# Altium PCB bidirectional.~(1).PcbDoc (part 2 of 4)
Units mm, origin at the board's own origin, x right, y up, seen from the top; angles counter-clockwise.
Board outline 190.5 x 127 mm, 6 copper layers (Top Layer, MidLayer1, MidLayer2, Mid-Layer 3, Mid-Layer 4, Bottom Layer), stack 2.997 mm thick; 416 components, 178 nets, 1084 pads, 2010 vias.
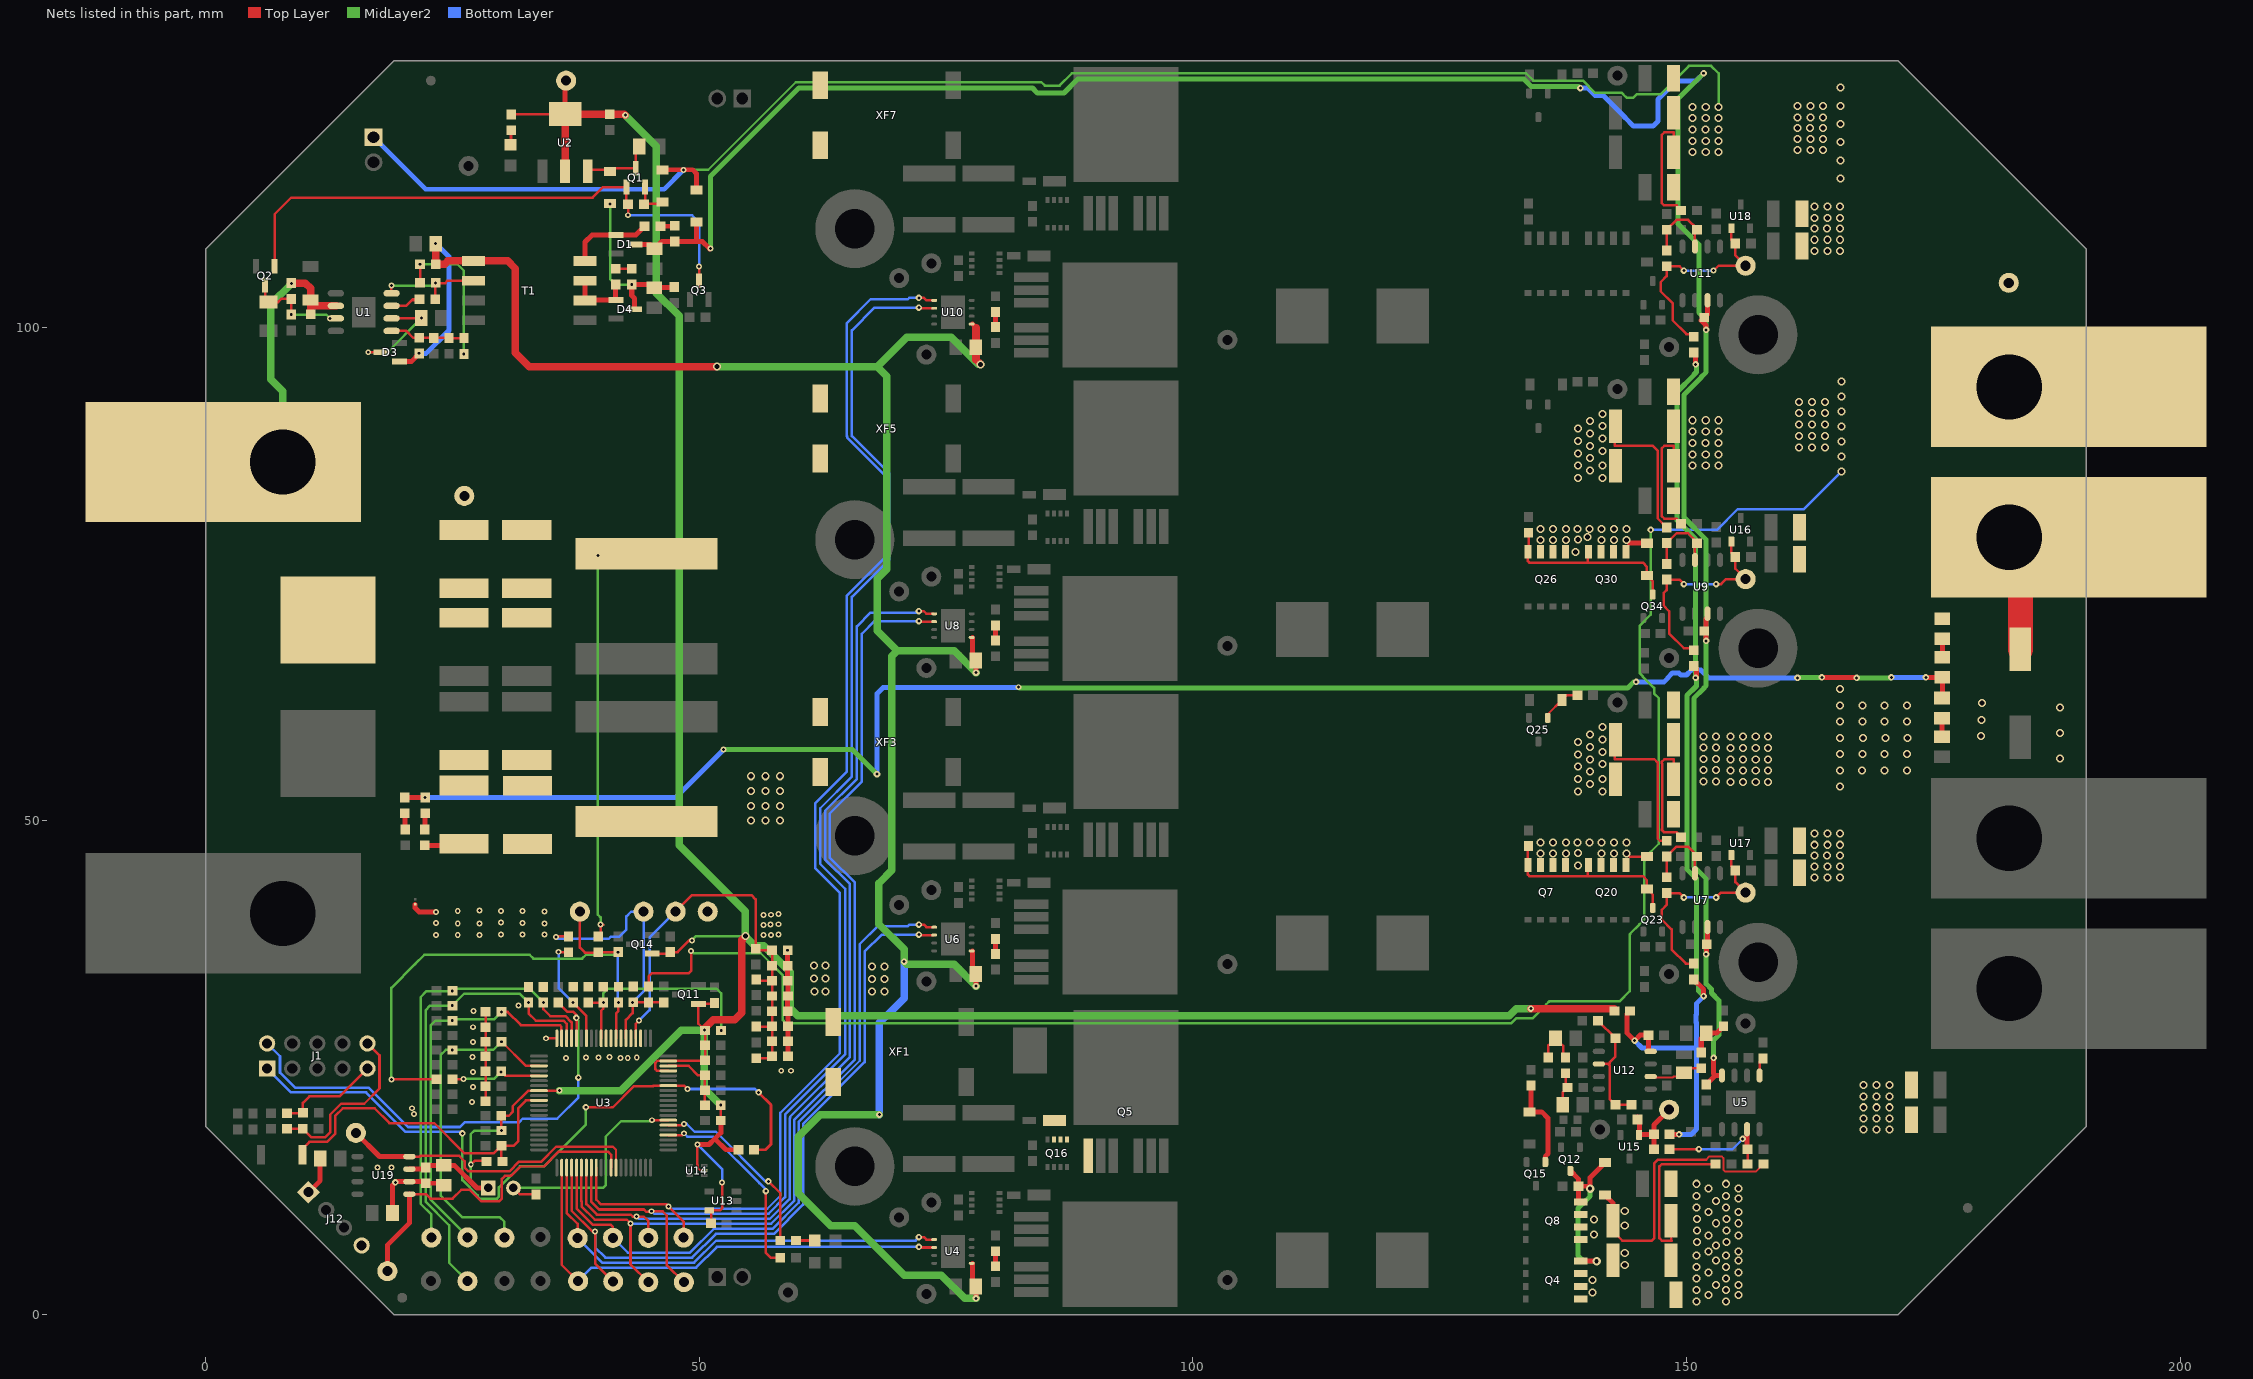
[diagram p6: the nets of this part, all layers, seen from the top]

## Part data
C1: "CAP, CERM, 3300pF, 100V, +/-5%, X7R, 0603"
C2 C8 C11: "CAP, CERM, 10uF, 16V, +/-20%, X5R, 0805"
C3: "CAP, CERM, 0.1uF, 50V, +/-10%, X7R, 0603"
C4 C28 C91 C93 C95 C97: "CAP, CERM, 0.1uF, 25V, +/-5%, X7R, 0603"
C5 C10 C114: "CAP, CERM, 100pF, 50V, +/-5%, C0G/NP0, 0603"
C6: "CAP, CERM, 2.2uF, 100V, +/-10%, X7R, 1206_190"
C7: "CAP, CERM, 0.47uF, 100V, +/-10%, X7R, 1206"
C9 C61 C70 C79 C88 C99 C100 C101 C102: "CAP, CERM, 2.2uF, 16V, +/-10%, X5R, 0805"
C12: "CAP, CERM, 10uF, 25V, +/-10%, X5R, 0805"
C13: "CAP, CERM, 10uF, 6.3V, +/-20%, X5R, 0603"
C14 C15: "CAP, CERM, 33pF, 100V, +/-5%, C0G/NP0, 0603"
C16 C25 C27 C63 C72 C81 C115: "CAP, CERM, 0.01uF, 100V, +/-5%, X7R, 0603"
C17 C20 C23: "CAP, CERM, 1uF, 16V, +/-10%, X5R, 0603"
C18 C19 C21 C24 C90: "CAP, CERM, 0.1uF, 16V, +/-5%, X7R, 0603"
C22 C71 C80 C89 C94: "CAP, CERM, 2.2uF, 10V, +/-10%, X5R, 0603"
C26 C103: "CAP, CERM, 0.022uF, 25V, +/-10%, X7R, 0603"
C29 C30 C31: "CAP, CERM, 2.2uF, 6.3V, +/-10%, X5R, 0603"
C32 C34 C35 C36 C104: "CAP, CERM, 22pF, 50V, +/-5%, C0G/NP0, 0603"
C33: "CAP, CERM, 100pF, 25V, +/-10%, X7R, 0603"
C37 C38 C40 C41 C49 C50 C52 C53: "CAP, CERM, 22uF, 50V, +/-20%, X5R, 6x5x5mm"
C39 C60 C69 C78 C87: "CAP, CERM, 0.1uF, 25V, +/-10%, X7R, 0603"
C39 C45 C51 C57: "CAP, CERM, 1000pF, 100V, +/-5%, X7R, 0603"
C42 C54 C64 C66 C73 C75 C82 C84: "CAP, CERM, 10uF, 100V, +/-20%, X7S, 2220"
C43 C46 C55 C58: "CAP, CERM, 1uF, 16V, +/-10%, X7R, 0805"
C44 C56 C65 C67 C74 C76 C83 C85 C116 C117 C118 C119 C120 C121 C122 C123: "CAP, CERM, 47uF, 16V, +/-20%, X5R, 1210"
C47: "CAP, AL, 330uF, 100V, +/-20%,  ohm, SMD"
C48: "CAP, AL, 470uF, 25V, +/-20%,  ohm, SMD"
C59 C68 C77 C86: "CAP, CERM, 330pF, 50V, +/-5%, C0G/NP0, 0603"
C62: "CAP, CERM, 4.7uF, 25V, +/-10%, X5R, 0805"
C105: "CAP, CERM, 330pF, 100V, +/-5%, X7R, 0603"
C106 C108 C109 C112: "CAP, CERM, 1 µF, 25 V, +/- 10%, X7R, 0603_095"
C107 C110 C111 C113: "CAP, CERM, 1000 pF, 50 V, +/- 10%, X7R, 0603"
D1 D3 D4: "Diode, Switching, 200V, 0.2A, SOT-23"
D2 D7 D16: "LED, Red, SMD"
D5 D6 D17: "Diode, Schottky, 40 V, 0.5 A, SOD-123"
D8 D9 D10 D11 D12 D14 D15 D18: "Diode, Zener, 12V, 500mW, SOD-123"
D13 D19 D20 D21 D22 D23 D24 D25: "Diode, Schottky, 15 V, 1 A, DO-216-AA"
FID1 FID2 FID3: "Fiducial mark.  There is nothing to buy or mount."
H1 H2 H3 H4 H5 H6 H7: "Machine Screw, Round, #4-40 x 1/4, Nylon, Philips panhead"
J1: "Header (shrouded), 100mil, 5x2, Gold, TH"
J2 J3 J4 J5 J6 J7: "Connector Lug, wire range #6 - 4/0, 600V"
J8 J9 J11: "Header,2x1, 100mil, TH"
J10: "Header, 2x1, 100mil, SMT"
J12: "Header, TH, 100mil, 4x1, Gold plated, 230 mil above insulator"
L1 L2: "Inductor, Shielded, Composite, 1uH, 57.5A, 0.000929 ohm, SMD"
L3 L4 L5 L6: "Inductor, Shielded Drum Core, Ferrite, 2.2uH, 30A, 0.00183 ohm, SMD"
LBL1: library part THT-14-423-10, "Thermal Transfer Printable Labels, 0.650\" W x 0.200\" H - 10,000 per roll"
Logo1: library part TI_Logo, "Texas Instrument Corporate Signature"
Logo2: library part Pb-Free
Logo3: library part FCC_disclaimer, "FCC_disclaimer"
Logo4 Logo5: library part IEC_HighVoltage, "IEC 61010-1 High Voltage Warning"
Logo6: library part IEC_HotSurface, "IEC 61010-1 Hot Surface Warning"
NT1: "Single point connection between nets."
Q1: "MOSFET, P-CH, -20V, -2.4A, SOT-23"
Q2 Q3 Q11 Q12 Q14 Q23 Q34 Q43: "MOSFET, N-CH, 60V, 0.24A, SOT-23"
Q4 Q7 Q8 Q9 Q20 Q26 Q30 Q39: "MOSFET, N-CH, 30V, 51A, SON 5x6mm"
Q5 Q6 Q18 Q22 Q28 Q32 Q38 Q42: "MOSFET, N-CH, 80 V, 180 A, DDPAK-7"
Q15 Q25 Q35 Q45: "MOSFET, P-CH, -100V, -0.6A, SOT-23"
Q16 Q17 Q24 Q27 Q36 Q37 Q46 Q47: library part "ECH8102-TL-H, ON Semiconductor", "Transistor, PNP, 30 V, 12 A, SMD-8"
R1 R16: "RES, 330 ohm, 1%, 0.1W, 0603"
R2: "RES, 39.0k ohm, 1%, 0.1W, 0603"
R3: "RES, 150k ohm, 1%, 0.1W, 0603"
R4: "RES, 120k ohm, 1%, 0.1W, 0603"
R5 R122: "RES, 49.9 ohm, 1%, 0.1W, 0603"
R6: "RES, 27.0k ohm, 1%, 0.1W, 0603"
R7 R118: "RES, 10.0k ohm, 1%, 0.1W, 0603"
R8 R9 R19 R34 R38 R40 R41 R42 R43 R45 R46 R56 R60 R61 R63 R64 R65 R75 R79 R80 R82 R83 R84 R94 R98 R99 R101 R102 R103 R124 R125 R126 R127: "RES, 1.0k ohm, 5%, 0.1W, 0603"
R10: "RES, 560 ohm, 1%, 0.1W, 0603"
R11: "RES, 3.0k ohm, 5%, 0.1W, 0603"
R12 R112 R116: "RES, 100 k, 5%, 0.1 W, 0603"
R13 R14: "RES, 1.50k ohm, 0.1%, 0.1W, 0603"
R15 R20 R21 R22 R23 R120: "RES, 0 ohm, 5%, 0.1W, 0603"
R17 R29 R111 R115 R117 R119: "RES, 1.00k ohm, 1%, 0.1W, 0603"
R24 R26: "RES, 100 ohm, 1%, 0.1W, 0603"
R27 R36 R52 R57 R71 R76 R90 R95: "RES, 0.002, 1%, 1 W, 2512"
R28: "RES, 1.10k ohm, 1%, 0.1W, 0603"
R30 R39 R53 R59 R72 R78 R91 R97: "RES, 10.0k ohm, 0.1%, 0.1W, 0603"
R33: "RES, 36.0k ohm, 1%, 0.1W, 0603"
R35: "RES, 8.06k ohm, 1%, 0.1W, 0603"
R43 R135: "RES, 0 ohm, 5%, 0.125W, 0805"
R44 R47 R49 R62 R66 R68 R81 R85 R87 R100 R104 R106: "RES, 26.1k ohm, 1%, 0.1W, 0603"
R48 R67 R86 R105: "RES, 40.2k ohm, 1%, 0.1W, 0603"
R51 R70 R89 R108: "RES, 1.65k ohm, 1%, 0.1W, 0603"
R109 R110 R113 R114: "RES, 2.00k ohm, 1%, 0.1W, 0603"
R121: "RES, 31.6k ohm, 1%, 0.1W, 0603"
R128: "RES, 75.0, 1%, 0.1 W, 0603"
R130: "RES, 10.0 ohm, 1%, 0.1W, 0603"
S1: "Switch, Push Button, SMD"
T1: library part XFMR_BSEPC10-138, "xfmr, ?0%"
TP1 TP2 TP4 TP5 TP6 TP7 TP8 TP9 TP10 TP11 TP13 TP14 TP15 TP16 TP17 TP18 TP19 TP20 TP21 TP22 TP23 TP24 TP25 TP26 TP27 TP28 TP29 TP31 TP32 TP33 TP35 TP36 TP37 TP38 TP39 TP40 TP41 TP42 TP43 TP44 TP45 TP46 TP47 TP48 TP49 TP50 TP51 TP52 TP53 TP55 TP56 TP57 TP58 TP59 TP60: "Test Point, Miniature, White, TH"
TP3: "Test Point, Compact, SMT"
U1: "IC, Integrated Secondary Side Bias Regulator"
U2: "FIXED LOW-DROPOUT VOLTAGE REGULATOR, DCY0003A"
U3: "UCD3138128PFC, PFC0080"
U4 U6 U8 U10: "IC, 120V Boot, 4A Peak, High Frequency High-Side Low-Side Driver"
U5: "1.1 nV/rtHz Noise, Low Power, Precision Operational Amplifier, 4.5 to 36 V, -40 to 125 degC, 8-pin SOP (DDA0008C), Green (RoHS & no Sb/Br)"
U7 U9 U11: "1.1 nV/rtHz Noise, Low Power, Precision Operational Amplifier, 4.5 to 36 V, -40 to 125 degC, 8-pin SOIC (D0008A), Green (RoHS & no Sb/Br)"
U12: "40-ns, microPOWER, Push-Pull Output Comparators, D0008A"
U13: "Single 2-Input Positive-AND Gate, DBV0005A"
U14: "DUAL BUFFER GATE, DRL0006A"
U15: "1 uA Shunt Voltage Reference, 1.25 V, 10 ppm / degC, 5 mA, -40 to 85 degC, 3-pin SOT-23 (DBZ), Green (RoHS & no Sb/Br)"
U16 U17 U18: library part REF1112AIDBZt, "1 uA Shunt Voltage Reference, 1.25 V, 10 ppm / degC, 5 mA, -40 to 85 degC, 3-pin SOT-23 (DBZ), Green (RoHS & no Sb/Br)"
U19: "3.3V CAN Transceiver with Standby Mode, Loop-back, 6 mA, -40 to 125 degC, 8-pin SOIC (D), Green (RoHS & no Sb/Br)"
XF1 XF3 XF5 XF7: "FuseHolder"
ZZ1: library part AssemblyNoteLabel
ZZ2 ZZ3 ZZ4: library part AssemblyNote

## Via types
v1: diameter 0.813, hole 0.508, Top Layer to Bottom Layer, 1661 vias
v2: diameter 0.6, hole 0.3, Top Layer to Bottom Layer, 178 vias
v3: diameter 0.66, hole 0.3, Top Layer to Bottom Layer, 84 vias
v4: diameter 0.66, hole 0.3, Top Layer to Bottom Layer, tented both sides, 35 vias
v5: diameter 0.5, hole 0.2, Top Layer to Bottom Layer, 20 vias
v6: diameter 0.813, hole 0.508, Top Layer to Bottom Layer, tented both sides, 10 vias
v7: diameter 0.66, hole 0.33, Top Layer to Bottom Layer, tented top, 8 vias
v8: diameter 0.6, hole 0.3, Top Layer to Bottom Layer, tented both sides, 7 vias
v9: diameter 0.813, hole 0.508, Top Layer to Bottom Layer, tented top, 5 vias
v10: diameter 0.864, hole 0.406, Top Layer to Bottom Layer, 2 vias

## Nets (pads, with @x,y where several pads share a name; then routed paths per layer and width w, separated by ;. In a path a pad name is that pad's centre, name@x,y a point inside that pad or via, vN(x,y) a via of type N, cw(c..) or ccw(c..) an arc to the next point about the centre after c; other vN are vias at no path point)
3.3VA: C16.1 C17.1 R15.1 U3.71 | length 22.3
  Top Layer w0.254: C17.1@38.735,31.61 v2(40.284,31.61) 40.284,31.001 40.06,30.776 U3.71@40.06,27.988
  MidLayer2 w0.254: v2(40.284,31.61) 40.284,32.563 40.742,33.02 51.74,33.02 52.222,32.537 v2(52.222,28.753)
3.3VD: C13.1 C18.1 C19.1 C20.1 C21.1 C22.2 C30.1 C31.2 C39.1@22.3,14.9 C62.1 J10.1 Q11.1 Q14.1 R9.2 R15.2 R17.1 R19.1 R38.2 R40.2 R130.2 TP11.1 U2.2 U2.4 U3.8 U3.57 U3.59 U13.5 U14.5 U19.3 | length 317.5
  Top Layer w0.2: 49.809,15.2 49.865,15.145 49.865,14.806 50.04,14.631 50.448,14.631 U14.5@50.499,14.58
  Top Layer w0.254: v2(26.848,15.189) 27.254,15.596 R19.1@28.359,15.596 ; v2(29.947,18.644) 29.934,18.656 C21.1@29.934,20.142 30.709,20.142 31.09,20.523 31.09,21.1 32.677,22.688 U3.8@33.76,22.688 35.809,22.688 v2(35.814,22.682) ; R9.2@30.937,121.577 36.39,121.577 36.398,121.585 U2.4@36.415,121.602 ; Q14.1@45.222,36.566 46.916,36.566 R38.2@47.066,36.716 47.79,36.716 48.971,37.897 v2(49.251,37.897) ; U3.57@46.86,24.688 45.721,24.688 45.542,24.867 45.542,25.502 45.728,25.688 U3.59@46.86,25.688 50.504,25.688 C19.1@50.572,25.756 50.597,25.781 C18.1@50.597,27.28 ; 49.809,15.2 v2(49.809,17.221) ; C18.1@50.572,27.28 C18.1@50.597,27.28 ; R15.2@50.584,28.778 49.906,29.456 Q11.1@49.906,31.473 51.45,31.473 R40.2@51.537,31.56 ; R15.2@50.597,28.778 C18.1@50.597,27.28 ; C31.2@51.156,9.233 C31.2@51.168,9.246 51.208,9.285 51.208,10.556 52.111,10.556 52.299,10.744 v2(52.299,13.36) ; C30.1@52.172,19.66 v2(52.172,21.209)
  Top Layer w0.5: U19.3@20.625,14.735 22.135,14.735 C39.1@22.3,14.9 22.516,15.116 C62.1@24.1,15.116 25.184,15.116 27.473,12.827 J10.1@28.626,12.827 ; U2.4@36.398,121.62 36.398,124.898 TP11.1@36.5,125 ; 51.575,17.818 52.699,16.694 R17.1@53.95,16.694
  Top Layer w0.508: v2(49.809,17.221) 50.978,17.221 51.575,17.818 52.172,18.415 C30.1@52.172,19.66
  Top Layer w0.762: U2.2@36.398,115.82 U2.4@36.398,121.585 ; U2.4@36.415,121.602 C13.1@40.919,121.602 42.398,121.602 v3(42.5,121.5) ; R15.2@50.584,28.778 50.584,29.051 51.421,29.888 53.586,29.888 54.28,30.582 54.28,37.948 v1(54.661,38.329) ; v3(134.25,31) 142.7,31 R130.2@142.7,30.75
  MidLayer2 w0.254: J10.1@28.626,12.827 27.432,12.827 26.848,13.411 v2(26.848,15.189) 26.848,18.288 27.203,18.644 v2(29.947,18.644) ; v2(49.251,37.897) 49.682,38.329 v1(54.661,38.329)
  MidLayer2 w0.762: v2(35.814,22.682) 42.062,22.682 48.184,28.804 v2(50.521,28.804) 50.521,22.86 v2(52.172,21.209) ; v3(42.5,121.5) 45.644,118.356 45.644,103.48 47.955,101.168 47.955,47.549 54.661,40.843 v1(54.661,38.329) 55.626,37.363 56.538,37.363 59.233,34.668 59.233,31.013 59.969,30.277 132.027,30.277 132.75,31 v3(134.25,31)
  Bottom Layer w0.254: v2(49.809,17.221) 52.299,14.732 v2(52.299,13.36)
3.3VP: C29.2 R51.1 R70.1 R89.1 R108.1 R130.1 U12.8 | length 101.7
  Top Layer w0.508: R130.1@144.3,30.75 143.988,30.438 143.988,28.512 v3(144.75,27.75) 145.313,28.313 C29.2@146.144,28.313 146.144,26.886 U12.8@146.375,26.655 ; R51.1@148.3,18.25 v3(149.25,18.25) ; R70.1@150.75,33.95 151.75,32.95 v3(151.75,32.25) ; R89.1@150.75,65.7 151,65.45 v3@151,64.5 ; R108.1@150.75,97.45 150.936,97.264 v3(150.936,96.262)
  MidLayer2 w0.508: v3(150.936,96.262) 151.012,96.186 151.012,95.482 150.76,95.23 150.76,95.212 150.745,95.197 150.745,95.167 149.042,93.464 149.042,80.458 150.936,78.564 v3(150.936,64.512) 150.977,64.512 150.977,64.35 151.012,64.316 151.012,63.684 150.043,62.715 150.043,45.111 151,44.154 151,33.619 151.236,33.383 151.236,32.764 v3(151.75,32.25)
  Bottom Layer w0.508: v3(144.75,27.75) 145.5,27 151.012,27 ; v3(149.25,18.25) 150.481,18.25 151.012,18.781 151.012,19.404 151.033,19.426 151.033,20.074 151.012,20.096 151.012,27 ; v3(151.75,32.25) 151.033,31.533 151.033,30.391 150.967,30.324 150.967,29.609 151.012,29.564 151.012,27
12VS: C1.1 C11.1 C61.1 C70.1 C79.1 C88.1 D3.1 R6.2 T1.5 U4.1 U6.1 U8.1 U10.1 | length 237.8
  Top Layer w0.254: C11.1@23.317,108.483 23.317,106.413 C1.1@23.637,106.734
  Top Layer w0.5: U4.1@77.686,5.193 77.686,3.18 C61.1@78.016,2.85 78.029,2.837 v4(78.029,1.629) ; U6.1@77.686,36.843 77.686,34.83 C70.1@78.016,34.5 78.016,33.292 v4(78.029,33.279) ; U8.1@77.686,68.593 77.686,66.58 C79.1@78.016,66.25 78.016,65.042 v4(78.029,65.029) ; U10.1@77.686,100.343 77.686,100.33 78.029,99.987
  Top Layer w0.508: D3.1@19.619,96.535 20.818,96.535 R6.2@21.641,97.358
  Top Layer w0.762: C11.1@23.304,108.471 C1.1@23.304,106.401 24.206,106.401 24.539,106.734 T1.5@27.116,106.734 30.604,106.734 31.369,105.969 31.369,97.434 32.766,96.037 v1(51.791,96.037) ; 78.029,99.987 78.029,96.721 v1(78.5,96.25)
  MidLayer2 w0.762: v1(51.791,96.037) 68.037,96.037 ; v4(68.25,20.25) 62.25,20.25 60,18 60,12.3 63.3,9 65.75,9 70.75,4 74.5,4 76.871,1.629 v4(78.029,1.629) ; v4(78.029,33.279) 75.808,35.5 71,35.5 v4(70.75,35.75) 70.75,37 68.2,39.55 68.2,43.7 69.5,45 69.5,66.713 70.037,67.25 ; v4(78.029,65.029) 75.808,67.25 70.037,67.25 ; v1(78.5,96.25) 78.25,96.25 75.5,99 71,99 68.037,96.037 ; 68.037,96.037 69,95.075 69,75.5 68.037,74.537 68.037,69.25 70.037,67.25
  Bottom Layer w0.508: v2(21.615,97.384) 22.327,97.384 24.638,99.695 24.638,107.163 v2(23.292,108.509)
  Bottom Layer w0.762: v4(68.25,20.25) 68.25,29.55 69.369,30.669 69.369,30.672 70.75,32.053 v4(70.75,35.75)
12VSEN: C27.1 R29.1 R35.2 R119.1 TP7.1 U3.66 | length 28.9
  Top Layer w0.254: v2(35.5,38.25) 35.55,38.3 R119.1@36.75,38.3 ; U3.66@42.56,27.988 42.56,29.86 43.231,30.531 v2(43.231,31.623) ; C27.1@43.307,31.636 44.844,31.636 R29.1@44.856,31.623 R35.2@46.406,31.623 R35.2@46.507,31.521
  Bottom Layer w0.254: v2(35.5,38.25) 35.677,38.073 40.841,38.073 41.018,38.25 41.871,38.25 42.621,39 42.621,40.335 43.104,40.818 TP7.1@44.348,40.818 44.348,32.741 v2(43.231,31.623)
12VSEN_ADC: C103.1 R119.2 U3.74 | length 10.9
  Top Layer w0.254: v2(35.75,36.75) 35.8,36.7 R119.2@36.75,36.7 ; v2(37.211,31.61) 38.56,30.262 U3.74@38.56,27.988
  Bottom Layer w0.254: v2(35.75,36.75) 35.75,33.071 v2(37.211,31.61)
16VS: C2.1 C91.1 C93.2 C95.2 C97.2 C114.1 D1.3 D17.1 U5.8 U7.7 U9.7 U11.7 | length 246.8
  Top Layer w0.508: D1.3@43.47,108.42 45.009,108.42 C2.1@45.466,107.963 46.203,108.7 C114.1@47.5,108.7 49.7,108.7 ; D17.1@49.7,110.662 49.7,108.7 ; v2@51.041,107.963 50.304,108.7 49.7,108.7 ; C91.1@152,23.3 152.925,24.225 ; v4(152,36.5) 152.05,36.55 C95.2@152.05,37.5 152.135,37.585 U7.7@152.135,39.25 ; v4(152,68.25) 152,70.5 152.135,70.635 U9.7@152.135,71 ; v4(152,99.75) 152,100.2 151.5,100.7 C97.2@151.8,101 152.135,101.335 U11.7@152.135,102.75 ; v3(152.75,26) 152.75,24.4 152.925,24.225 ; U5.8@153.595,24.225 152.925,24.225
  MidLayer2 w0.508: v2(51.13,108.001) 51.13,115.307 60.073,124.25 83.75,124.25 84.246,123.754 86.938,123.754 88.344,125.16 133.519,125.16 134.26,124.42 139.08,124.42 v3(139.25,124.25) ; 151.452,94.905 151.467,94.92 151.467,94.938 152,95.47 v4(152,99.75) 152,100.75 151.25,101.5 151.25,108.404 149.154,110.5 149.154,123.154 v3(151.75,125.75) ; 151.467,94.89 149.749,93.172 149.749,80.751 152,78.5 v4(152,68.25) 152,63.703 151.719,63.422 151.719,63.392 150.75,62.423 150.75,45.404 152,44.154 v4(152,36.5) 152,33.5 152.533,32.967 152.533,32.574 153.283,31.824 153.283,28.33 152.75,27.797 v3(152.75,26)
  Bottom Layer w0.508: v3(139.25,124.25) 140,124.25 140.75,123.5 141.565,123.5 143.75,121.315 143.75,121.285 144.644,120.391 146.606,120.391 147.109,120.894 147.109,123.109 148.967,124.967 150.967,124.967 v3(151.75,125.75)
48V_CON: C39.1@22.2,47.536 C40.1 C41.1 L2.2 XF1.1 XF1.2 XF3.1 XF3.2 XF5.1 XF5.2 XF7.1 XF7.2 | length 4
  Top Layer w0.508: C39.1@22.2,47.536 26.001,47.536 C40.1@26.162,47.698
  other v1: 61.646,32.741 62.763,32.741 67.5,32.75 68.75,32.75 67.5,34 68.75,34 61.62,34.061 62.763,34.061 67.5,35.25 68.75,35.25 61.62,35.382 62.763,35.382 55.245,50.038 56.718,50.038 58.191,50.038 55.245,51.537 56.718,51.537 58.191,51.537 55.245,53.035 56.718,53.035 58.191,53.035 55.245,54.534 56.718,54.534 58.191,54.534
48VSEN: C25.1 R28.1 R33.2 R117.1 TP6.1 U3.68 | length 55.1
  Top Layer w0.254: v2(18.796,23.825) R117.1@23.381,23.825 ; TP6.1@37.897,40.818 37.897,37.178 38.402,36.673 R28.1@39.75,36.673 ; R28.1@39.75,36.716 R33.2@41.783,36.716 ; U3.68@41.56,27.988 41.56,30.485 41.808,30.734 v2(41.808,31.61)
  MidLayer2 w0.254: v2(18.796,23.825) 18.796,33.101 21.2,35.505 21.205,35.505 22.149,36.449 32.801,36.449 33.198,36.052 38.131,36.052 38.528,36.449 41.504,36.449 v2(41.758,36.703)
  Bottom Layer w0.254: v2@41.758,31.661 v2(41.758,36.703)
48VSEN_ADC: C26.1 R117.2 U3.5 | length 9.3
  Top Layer w0.254: R117.2@24.981,23.825 26.06,23.825 v2(26.111,23.876) ; C26.1@29.934,24.638 30.384,24.188 U3.5@33.76,24.188
  MidLayer2 w0.254: v2(26.111,23.876) 29.21,23.876 v2(29.921,24.587)
AGND: C16.2 C17.2 C25.2 C26.2 C27.2 C39.2@22.3,13.3 C59.2 C62.2 C63.2 C68.2 C71.2 C72.2 C77.2 C80.2 C81.2 C86.2 C89.2 C90.2 C94.2 C103.2 J12.1 J12.4 NT1.1 R43.1@11.584,15.8 R48.1 R67.1 R86.1 R105.1 R135.2 TP8.1 U3.63 U3.65 U3.67 U3.69 U3.70 U3.80 U19.2 | length 35.7
  Top Layer w0.254: C59.2@28.347,21.628 C68.2@28.347,23.114 C77.2@28.347,26.162 C80.2@28.347,27.635 C86.2@28.347,29.108 C89.2@28.347,30.658 ; v2(34.471,27.988) U3.80@35.56,27.988
  Top Layer w0.5: J12.1@10.406,12.394 11.584,13.572 R43.1@11.584,15.8 ; R135.2@18.916,10.3 18.916,13.116 v4(19.2,13.4) 19.265,13.465 U19.2@20.625,13.465 22.135,13.465 C39.2@22.3,13.3 23.884,13.3 C62.2@24.1,13.084 ; NT1.1@21.2,41.546 21.2,41.2 21.608,40.792 v2(23.343,40.792)
  Top Layer w0.508: R48.1@58.953,36.893 C63.2@58.953,35.319 R105.1@58.953,33.82 58.966,33.807 C90.2@58.966,32.271 58.954,32.258 R86.1@58.954,30.721 58.966,30.709 C81.2@58.966,29.197 R67.1@58.966,27.673 C72.2@58.966,26.149
  other v2: 26.975,21.539 27.051,23.063 27.051,24.587 58.3,24.7 59.3,24.7 36.474,26.01 42,26 42.75,26 38.532,26.035 39.802,26.06 43.663,26.06 27.026,26.086 40.919,26.086 27.051,27.61 27.076,29.108 27.127,30.734 31.7,31.3 58.928,36.906 57.25,38.443 23.343,38.456 25.527,38.456 27.711,38.456 56.505,38.459 32.106,38.481 29.921,38.506 34.315,38.506 58,38.5 56.505,39.475 57.225,39.509 58,39.541 25.527,39.624 27.711,39.624 34.315,39.624 32.106,39.649 23.317,39.675 29.896,39.726 56.505,40.491 57.25,40.5 58,40.557 34.315,40.843 32.106,40.869 25.527,40.894 29.921,40.894 27.711,40.919
  other v8: 17.4,14.9 18.8,14.9 21.1,20.3 20.9,20.9
BAT_12V: C43.1 C44.1 C48.1 C56.1 C65.1 C67.1 C74.1 C76.1 C83.1 C85.1 C116.1 C117.1 C118.1 C119.1 C120.1 C121.1 C122.1 C123.1 D6.2 D17.2 J2.1 J4.1 J11.1 R27.2 R29.2 R36.2 R43.1@152.95,15.25 R52.2 R57.2 R61.1 R71.2 R76.2 R80.1 R90.2 R95.2 R99.1 TP5.1 | length 402.8
  Top Layer w0.254: R29.2@44.856,33.223 44.856,34.265 45.187,34.595 48.946,34.595 49.174,34.823 v2(49.174,36.83) ; 148.45,7.724 148.45,7.55 148.5,7.5 147.5,7.5 147.25,7.75 147.25,15 147.499,15.249 152.184,15.249 152.185,15.25 R43.1@152.95,15.25 ; R52.2@148.7,54 148.7,56.25 147.75,56.25 147.521,56.021 147.521,55.825 147.525,55.821 147.525,49.179 147.521,49.175 147.521,49.079 147.725,48.875 149,48.875 R61.1@149.45,48.425 ; R71.2@148.7,85.75 148.7,88 147.75,88 147.521,87.771 147.521,80.859 147.755,80.625 149,80.625 R80.1@149.45,80.175 ; R90.2@148.7,117.5 148.7,119.75 147.75,119.75 147.521,119.521 147.521,112.579 147.725,112.375 149,112.375 R99.1@149.45,111.925
  Top Layer w0.5: D6.2@46.279,115.976 49.324,115.976 49.7,115.6 D17.2@49.7,113.937
  Top Layer w1.524: J4.1@187.579,78.613 J4.1@187.706,78.74
  Top Layer w2.032: J4.1@187.325,78.613 J4.1@187.452,78.74
  Top Layer w2.54: C48.1@183.82,67.391 183.82,75.362 J4.1@187.198,78.74
  MidLayer2 w0.254: v2@48.387,115.976 50.902,115.976 59.766,124.841 84.659,124.841 85,124.5 86.5,124.5 87.75,125.75 133.75,125.75 134.5,125 139.5,125 140.75,123.75 143.45,123.75 143.574,123.626 143.585,123.626 143.961,123.25 144.6,123.25 144.95,123.6 147.35,123.6 150.25,126.5 152.5,126.5 153.25,125.75 v1(153.25,122.347) ; v2(49.174,36.83) 49.2,36.83 49.428,36.601 56.222,36.601 58.471,34.353 58.471,29.82 58.776,29.515 132.265,29.515 132.75,30 134.389,30 135.797,31.408 135.797,31.438 136.062,31.703 136.092,31.703 136.139,31.75 143.25,31.75 144.25,32.75 144.25,38.5 144.297,38.547 144.297,38.577 145.229,39.509 145.229,39.539 145.729,40.039 145.729,45.968 145.75,45.99 145.75,46.25 147.193,47.693 147.193,62.443 146.732,62.903 146.732,63.482 145.567,64.648 145.567,64.685 145.25,65.001 145.25,69.771 146.385,70.906 v3(146.385,79.5) v3@146.25,79.5 ; v3@146.182,79.5 v3@146.25,79.5 ; v3@146.317,79.433 v3@146.25,79.5
  Bottom Layer w0.254: v3(146.385,79.5) 153.1,79.5 155.2,81.6 161.889,81.6 v1(165.71,85.42) ; J4.1@181.942,79.5 J4.1@182.702,78.74
  Bottom Layer w0.5: J11.1@17,119.27 22.27,114 46.436,114 v2(48.387,115.951)
  other v1: 151,1.326 154,1.326 152.25,2 155.25,2 151,2.469 154,2.469 153,3 155.25,3 151,3.638 154,3.638 152.25,4.25 155.25,4.25 151,4.806 154,4.806 153,5.5 155.25,5.5 151,6 154,6 152.25,6.374 155.25,6.374 153,7 151.051,7.352 154.051,7.352 152.25,8 155.25,8 151.051,8.495 154.051,8.495 153,9.25 155.25,9.25 151.051,9.663 154.051,9.663 152.25,10.413 155.25,10.413 151.025,10.832 154.025,10.832 153,11.5 155.25,11.75 151,12 154,12 152.25,12.75 155.25,12.75 151,13.25 154,13.25 167.955,18.765 169.275,18.765 170.571,18.765 167.955,19.882 169.275,19.882 170.571,19.882 167.955,21 169.25,21 170.571,21 167.955,22.092 169.275,22.092 170.571,22.092 167.955,23.235 169.275,23.235 170.571,23.235 162.955,44.265 164.275,44.265 165.571,44.265 162.955,45.382 164.275,45.382 165.571,45.382 162.955,46.5 164.25,46.5 165.571,46.5 162.955,47.592 164.275,47.592 165.571,47.592 162.955,48.735 164.275,48.735 165.571,48.735 165.557,53.492 154.455,53.964 155.75,53.964 157.02,53.964 158.25,53.964 151.73,54 153,54 154.455,55.107 155.75,55.107 157.02,55.107 158.25,55.107 165.557,55.118 167.767,55.118 170.078,55.118 172.339,55.118 151.73,55.143 153,55.143 154.455,56.25 155.75,56.25 157.02,56.25 158.25,56.25 151.73,56.286 153,56.286 187.858,56.312 165.557,56.769 167.818,56.769 170.078,56.769 172.339,56.769 154.455,57.393 155.75,57.393 157.02,57.393 158.25,57.393 151.73,57.429 153,57.429 165.557,58.42 167.894,58.42 170.18,58.42 172.415,58.42 154.455,58.536 155.75,58.536 157.02,58.536 158.25,58.536 151.73,58.572 153,58.572 179.857,58.623 187.858,58.903 165.557,60.071 167.818,60.071 170.078,60.071 172.339,60.071 179.908,60.223 187.858,61.493 165.557,61.722 167.818,61.722 170.078,61.722 172.339,61.722 179.934,61.976 165.557,63.348 150.608,86 151.955,86 153.25,86 165.71,86.919 150.634,87.143 151.955,87.143 153.25,87.143 161.392,87.859 162.738,87.859 164.033,87.859 150.634,88.311 151.929,88.311 153.25,88.311 165.71,88.443 161.417,89.002 162.738,89.002 164.033,89.002 150.634,89.454 151.955,89.454 153.25,89.454 165.71,89.967 161.417,90.17 162.712,90.17 164.033,90.17 150.634,90.597 151.955,90.597 153.25,90.597 161.417,91.313 162.738,91.313 164.033,91.313 165.71,91.491 161.417,92.456 162.738,92.456 164.033,92.456 165.71,93.015 165.71,94.513 162.955,107.765 164.275,107.765 165.571,107.765 162.955,108.882 164.275,108.882 165.571,108.882 162.955,110 164.25,110 165.571,110 162.955,111.092 164.275,111.092 165.571,111.092 162.955,112.235 164.275,112.235 165.571,112.235 165.608,115.087 165.608,116.916 150.608,117.75 151.955,117.75 153.25,117.75 161.239,117.958 162.56,117.958 163.855,117.958 165.608,118.77 150.634,118.893 151.955,118.893 153.25,118.893 161.239,119.075 162.56,119.075 163.855,119.075 150.634,120.061 151.929,120.061 153.25,120.061 161.239,120.193 162.535,120.193 163.855,120.193 165.608,120.599 150.634,121.204 151.955,121.204 153.25,121.204 161.239,121.285 162.56,121.285 163.855,121.285 150.634,122.347 151.955,122.347 161.239,122.428 162.56,122.428 163.855,122.428 165.608,122.453 165.608,124.308
BAT_48V: C6.1 C37.1 C38.1 C47.1 J3.1 L1.1 R3.2 R4.1 R28.2 TP2.1 U1.2 | length 66.6
  Top Layer w0.254: R28.2@39.75,38.3 40,38.55 v2@40,39.25 ; v2(40,39.5) v2@40,39.25 ; v2@40.25,39.5 v2@40,39.25
  Top Layer w0.762: R3.2@8.687,104.483 10.097,104.483 10.617,103.962 C6.1@10.617,102.77 ; R4.1@10.617,101.333 C6.1@10.617,102.77 ; U1.2@13.208,102.184 11.203,102.184 C6.1@10.617,102.77
  MidLayer2 w0.254: v2(39.726,76.911) 39.726,40.5 40,40.226 v2@40,39.75 ; v2(40,39.5) v2@40,39.75 ; v2@40.25,39.5 v2@40,39.75
  MidLayer2 w0.762: J3.1@7.798,86.36 7.798,93.523 6.579,94.742 6.579,102.337 v2(8.687,104.445)
BIAS_CTR: Q1.1 Q2.1 Q3.3 R8.1 | length 58.4
  Top Layer w0.254: Q2.1@6.97,106.208 6.97,111.465 8.661,113.157 39.192,113.157 40.249,114.214 Q1.1@42.611,114.214 42.611,112.647 R8.1@42.786,112.471 v2(42.786,111.366) ; Q3.3@49.987,104.734 v2(49.987,106.172)
  Bottom Layer w0.254: v2(42.786,111.366) 49.263,111.366 49.987,110.642 v2(49.987,106.172)
BOOST: R16.2 U3.44 | length 20.4
  Top Layer w0.254: U3.44@46.86,18.188 48.261,18.188 v2(48.438,18.364) ; v4(56.75,12.5) 56.75,6.25 57.25,5.75 R16.2@58.2,5.75
  Bottom Layer w0.254: v2(48.438,18.364) 48.793,18.009 51.391,18.009 56.075,13.325 56.75,12.65 v4(56.75,12.5)
BP18: C22.1 C23.1 C24.1 U3.58 | length 7.1
  Top Layer w0.254: U3.58@46.86,25.188 48.93,25.188 49.886,24.232 C24.1@50.572,24.232 C23.1@50.572,22.733 50.546,22.708 C22.1@50.546,21.209
BUCK: R1.2 U3.46 | length 19.1
  Top Layer w0.254: U3.46@46.86,19.188 48.296,19.188 v2(48.43,19.322) ; v4(57,13.5) 58.2,12.3 R1.2@58.2,7.5
  Bottom Layer w0.254: v2(48.43,19.322) 48.725,19.322 49.53,18.517 51.683,18.517 56.7,13.5 v4(57,13.5)
CAN_RX: TP59.1 U3.33 U19.4 | length 31.4
  Top Layer w0.25: U19.4@20.625,16.005 21.68,16.005 21.75,16.075 25.675,16.075 26.219,15.531 26.219,14.893 26.612,14.5 30.75,14.5 31.75,15.5 34,15.5 35.5,17 41.25,17 41.56,16.69 U3.33@41.56,14.888
  Top Layer w0.5: TP59.1@15.2,18.4 17.595,16.005 U19.4@20.625,16.005
CAN_TX: TP60.1 U3.32 U19.1 | length 34.8
  Top Layer w0.25: U19.1@20.625,12.195 22.305,12.195 22.75,11.75 25,11.75 25.879,12.629 26.76,12.629 27.889,11.5 29.75,11.5 30,11.75 30,13.75 30.301,14.051 30.936,14.051 31.885,15 34.25,15 35.75,16.5 40.75,16.5 41.06,16.19 U3.32@41.06,14.888
  Top Layer w0.5: TP60.1@18.4,4.4 18.4,7.025 20.625,9.25 U19.1@20.625,12.195
CUR_CMD: C115.1 J1.2 U3.76 | length 50.1
  Top Layer w0.254: C115.1@35.7,31.6 36.6,30.7 37.2,30.7 v4@37.56,30.34 ; U3.76@37.56,27.988 v4@37.56,30.044
  MidLayer2 w0.254: v4(37.544,30.044) 37.5,30 37.75,29.75 v4(37.75,24)
  Bottom Layer w0.254: J1.2@6.22,27.47 7.52,26.17 7.52,24.52 9.041,23 16.5,23 20.5,19 25.712,19 25.728,19.016 25.766,19.016 26.25,19.5 31.765,19.5 32.098,19.833 35.583,19.833 37.75,22 v4(37.75,24) v4@37.75,24.25
DIRECTION: J1.1 R17.2 U3.54 | length 72.4
  Top Layer w0.254: v4(38.5,21) 41.25,21 43.394,23.144 45.321,23.144 45.365,23.188 U3.54@46.86,23.188 48.466,23.188 v2(48.793,22.86)
  Top Layer w0.3: R17.2@55.55,16.694 56.694,16.694 57.25,17.25 57.25,21.25 v4(56,22.5)
  MidLayer2 w0.254: v4(26,18.36) 26,13.618 27.55,12.069 27.55,11.942 27.741,11.751 29.511,11.751 29.702,11.942 29.702,12.885 31.817,15 34.25,15 38.5,19.25 v4(38.5,21)
  Bottom Layer w0.254: J1.1@6.22,24.93 8.65,22.5 16.25,22.5 20.25,18.5 25.86,18.5 v4(26,18.36)
  Bottom Layer w0.3: v2(48.793,22.86) 55.64,22.86 v4(56,22.5)
DPWM0A: TP15.1 U3.22 U4.6 | length 49.6
  Top Layer w0.254: U3.22@36.06,14.888 36.06,5.037 TP15.1@37.719,3.378 ; v3(72.25,6.85) 72.307,6.793 U4.6@73.698,6.793
  Bottom Layer w0.254: TP15.1@37.719,3.378 39.091,4.75 49.679,4.75 51.779,6.85 v3(72.25,6.85)
DPWM0B: TP19.1 U3.23 U4.5 | length 45.8
  Top Layer w0.254: U3.23@36.56,14.888 36.56,10.303 37.668,9.195 TP19.1@37.668,7.747 ; v3(72.25,7.85) 72.75,7.85 73.007,7.593 U4.5@73.698,7.593
  Bottom Layer w0.254: TP19.1@37.668,7.747 40.157,5.258 49.468,5.258 51.71,7.5 71.9,7.5 v3(72.25,7.85)
DPWM1A: TP28.1 U3.24 U6.6 | length 74.7
  Top Layer w0.254: U3.24@37.06,14.888 37.06,10.514 39.179,8.395 v2@39.408,8.395 ; v2@39.446,8.306 39.446,5.182 TP28.1@41.275,3.353 ; v3(72.25,38.5) 72.307,38.443 U6.6@73.698,38.443
  MidLayer2 w0.254: v2(39.446,8.433) v2@39.446,8.534
  Bottom Layer w0.254: v2(39.446,8.433) 39.446,6.807 40.488,5.766 49.258,5.766 51.671,8.179 57.546,8.179 60.506,11.139 60.506,19.325 66.75,25.569 66.75,36.762 68.488,38.5 v3(72.25,38.5)
DPWM1B: TP32.1 U3.25 U6.5 | length 68.4
  Top Layer w0.254: U3.25@37.56,14.888 37.56,10.752 39.193,9.119 41.021,9.119 41.25,8.89 TP32.1@41.25,7.772 ; v3(72.25,39.5) 72.75,39.5 73.007,39.243 U6.5@73.698,39.243
  Bottom Layer w0.254: TP32.1@41.25,7.772 42.748,6.274 49.047,6.274 51.46,8.687 57.413,8.687 60.053,11.327 60.053,19.512 66.25,25.709 66.25,37.52 68.087,39.357 71.138,39.357 71.281,39.5 v3(72.25,39.5)
DPWM2A: TP41.1 U3.26 U8.6 | length 104.1
  Top Layer w0.254: U3.26@38.06,14.888 38.06,11.47 38.068,11.462 38.068,10.963 39.404,9.627 42.647,9.627 v2(43.028,9.246) 43.028,5.08 TP41.1@44.831,3.277 ; v3(72.25,70.25) 72.307,70.193 U8.6@73.698,70.193
  Bottom Layer w0.254: v2(43.028,9.246) 43.078,9.195 57.281,9.195 59.6,11.514 59.6,19.7 65.75,25.85 65.75,43.75 63.203,46.297 63.203,50.731 66.472,54 66.472,68.972 67.75,70.25 v3(72.25,70.25)
DPWM2B: TP45.1 U3.27 U8.5 | length 100.2
  Top Layer w0.254: U3.27@38.56,14.888 38.56,11.189 39.614,10.135 43.053,10.135 43.256,9.931 v2(43.637,9.931) 44.374,9.931 44.831,9.474 TP45.1@44.831,7.772 ; v3(72.25,71.25) 72.75,71.25 73.007,70.993 U8.5@73.698,70.993
  Bottom Layer w0.254: v2(43.637,9.931) 43.866,9.703 57.148,9.703 59.147,11.702 59.147,19.888 59.2,19.941 59.2,20.036 65.25,26.086 65.25,43.609 62.75,46.109 62.75,51.036 65.964,54.25 65.964,69.714 67.35,71.1 72.1,71.1 v3(72.25,71.25)
DPWM3A: TP52.1 U3.28 U10.6 | length 138.6
  Top Layer w0.254: U3.28@39.06,14.888 39.06,11.423 39.841,10.643 44.381,10.643 44.61,10.414 45.11,10.414 v2(45.161,10.465) 46.279,10.465 46.685,10.058 46.685,5.029 TP52.1@48.438,3.277 ; v3(72.25,102) 72.307,101.943 U10.6@73.698,101.943
  Bottom Layer w0.254: v2(45.161,10.465) 45.415,10.211 57.015,10.211 58.694,11.89 58.694,20.075 58.7,20.081 58.7,20.279 64.773,26.352 64.773,43.133 62.25,45.656 62.25,51.294 65.456,54.5 65.456,72.706 69.25,76.5 69.25,85.206 65.456,89 65.456,99.706 67.75,102 v3(72.25,102)
DPWM3B: TP56.1 U3.29 U10.5 | length 133
  Top Layer w0.254: U3.29@39.56,14.888 39.56,11.642 40.051,11.151 46.685,11.151 v2(46.888,10.947) 48.412,9.423 TP56.1@48.412,7.798 ; v3(72.25,103) 72.75,103 73.007,102.743 U10.5@73.698,102.743
  Bottom Layer w0.254: v2(46.888,10.947) 47.117,10.719 56.883,10.719 58.2,12.036 58.2,20.42 64.25,26.47 64.25,42.703 61.75,45.203 61.75,51.802 64.948,55 64.948,72.838 68.797,76.688 68.797,85.018 65.003,88.812 65.003,88.945 64.948,89 64.948,100.448 67.357,102.857 71.138,102.857 71.281,103 v3(72.25,103)
E: C45.2 C46.2 C51.1 C55.1 | length 170.5
  Top Layer w0.508: C51.1@20.168,52.387 v2(22.225,52.387) ; v3(163.709,64.541) 167.209,64.541 v3(167.25,64.5) ; v3(174.25,64.541) C46.2@175.92,64.541 175.92,62.484 C55.1@175.895,62.459
  MidLayer2 w0.508: v2(52.451,57.226) 65.524,57.226 v4(68,54.75) ; v2(82.347,63.551) 82.423,63.475 144.039,63.475 144.661,64.096 v3(144.91,64.096) ; v3(161.25,64.5) 161.291,64.541 v3(163.709,64.541) ; v3(167.25,64.5) v3@170.709,64.5
  Bottom Layer w0.508: v2(22.225,52.387) 47.612,52.387 v2(52.451,57.226) ; v4(68,54.75) 68,62.9 68.6,63.5 v2@82.245,63.5 ; v3(144.91,64.096) 147.739,64.096 148.117,64.474 148.117,64.524 148.576,64.983 149.224,64.983 149.424,64.783 150.009,64.783 150.5,65.274 150.59,65.274 150.611,65.295 151.26,65.295 151.281,65.274 151.476,65.274 152.25,64.5 v3(161.25,64.5) ; v3(170.75,64.541) v3(174.25,64.541)
I_SENSE: C63.1 C72.1 C81.1 C90.1 R47.1 R48.2 R66.1 R67.2 R85.1 R86.2 R104.1 R105.2 TP18.1 U3.64 | length 46.1
  Top Layer w0.254: U3.64@43.56,27.988 43.56,29.437 v2(43.891,29.769) ; TP18.1@47.6,40.818 49.276,42.494 55.27,42.494 55.702,42.062 R47.1@55.702,37.058 55.867,36.893 R48.2@57.353,36.893 ; R66.1@55.753,25.959 55.766,25.946 57.404,25.946 R67.2@57.404,27.531 ; R85.1@55.753,29.172 57.379,29.172 C81.1@57.404,29.197 ; R104.1@55.753,33.96 55.893,33.82 R105.2@57.353,33.82 ; R48.2@57.404,36.843 C81.1@57.404,29.197 ; R67.2@57.45,27.531 R67.2@57.404,27.531 ; R67.2@57.404,27.531 C81.1@57.404,29.197
  Bottom Layer w0.254: v2(43.891,29.769) 44.958,30.836 44.958,38.176 TP18.1@47.6,40.818
IOUT_1: C94.1 R45.2 TP16.1 U3.77 | length 44.5
  Top Layer w0.254: TP16.1@22.86,7.798 TP16.1@22.86,8.433 ; v8(34.2,31.6) 34.2,30.926 34.9,30.226 36.435,30.226 37.013,29.648 37.013,29.647 37.06,29.6 U3.77@37.06,27.988
  MidLayer2 w0.254: TP16.1@22.86,7.798 22.86,10.124 21.755,11.229 21.755,32.144 22.377,32.766 v2(24.968,32.766) 25.222,33.02 32.78,33.02 v8(34.2,31.6)
IOUT_2: C71.1 R64.2 TP29.1 U3.78 | length 47.6
  Top Layer w0.254: v8(32.7,31.6) 32.7,30.5 33.427,29.773 36.247,29.773 36.56,29.46 U3.78@36.56,27.988
  MidLayer2 w0.254: TP29.1@26.518,3.378 24.663,5.232 24.663,9.039 22.263,11.439 22.263,30.823 22.733,31.293 v2(24.968,31.293) 26.187,32.512 31.788,32.512 v8(32.7,31.6)
IOUT_3: C80.1 R83.2 TP42.1 U3.3 | length 34.9
  Top Layer w0.254: v2(29.947,27.635) 29.987,27.635 32.427,25.196 32.751,25.196 ; 32.751,25.188 U3.3@33.76,25.188
  MidLayer2 w0.254: v2(29.947,27.635) 29.134,26.822 v2(24.968,26.822) 24.333,26.822 23.787,26.276 23.787,12.071 25.977,9.881 29.769,9.881 30.251,9.398 TP42.1@30.251,7.798
IOUT_4: C89.1 R102.2 TP53.1 U3.79 | length 38.9
  Top Layer w0.254: TP53.1@26.238,7.823 TP53.1@26.518,7.823 ; v2(29.947,30.658) 30.582,30.658 31.92,29.32 35.869,29.32 36.036,29.153 36.036,28.012 U3.79@36.06,27.988
  MidLayer2 w0.254: TP53.1@26.518,7.823 26.518,7.903 22.771,11.65 22.771,29.273 23.266,29.769 v2(24.968,29.769) 25.095,29.896 29.185,29.896 v2(29.947,30.658)
MASTER/SLAVE: J10.2 R118.2 U3.47 | length 24
  Top Layer w0.254: J10.2@31.166,12.827 31.813,12.179 R118.2@33.452,12.179 ; v2(45.215,19.688) U3.47@46.86,19.688
  MidLayer2 w0.254: J10.2@31.166,12.827 40.259,12.827 40.513,13.081 40.513,18.013 42.088,19.588 45.115,19.588 v2(45.215,19.688)
NetC1_2: C1.2 C3.1 R2.2 | length 15
  Top Layer w0.254: R2.2@21.704,104.521 C1.2@21.704,106.401
  MidLayer2 w0.254: v2(21.692,106.401) 25.502,106.401 26.137,105.766 v2(26.137,97.307)
NetC3_2: C3.2 C10.1 R6.1 R11.2 U1.5 | length 7.7
  Top Layer w0.254: U1.5@18.796,99.644 20.32,99.644 21.006,98.958 R6.1@21.641,98.958 21.666,98.933 R11.2@23.114,98.933 C10.1@24.638,98.933 24.651,98.92 C3.2@26.162,98.92
NetC4_1: C4.1 R2.1 T1.6 U1.8 | length 10.9
  Top Layer w0.254: U1.8@18.796,103.454 v2(18.796,104.242) ; C4.1@23.254,102.87 23.254,104.432 23.292,104.47 24.232,104.47 24.495,104.734 T1.6@27.116,104.734
  MidLayer2 w0.254: v2(18.796,104.242) 23.012,104.242 v2(23.292,104.521)
NetC4_2: C4.2 U1.7 | length 3.9
  Top Layer w0.254: U1.7@18.796,102.184 20.295,102.184 20.853,102.743 ; C4.2@21.654,102.743 20.853,102.743 ; C4.2@21.654,102.87 20.98,102.87 20.853,102.743
NetC5_1: C5.1 C8.1 D4.3 D5.2 R10.2 | length 17.1
  Top Layer w0.508: D4.3@43.444,101.841 43.444,102.936 43.155,103.226 v2(43.155,104.343) 45.123,104.343 C8.1@45.441,104.026 47.409,104.026 R10.2@47.473,104.089
  MidLayer2 w0.254: v2(40.97,112.522) 40.97,104.927 41.554,104.343 v2(43.155,104.343)
NetC5_2: C5.2 R5.2 | length 1.6
  Top Layer w0.254: R5.2@41.529,105.943 C5.2@43.155,105.943
NetC7_1: C7.1 Q2.3 R3.1 R7.2 U1.3 | length 10
  Top Layer w0.254: Q2.3@6.02,104.308 6.02,102.898 C7.1@6.35,102.567 7.317,102.567 7.633,102.883 R3.1@8.661,102.883 v2(8.661,101.308)
  MidLayer2 w0.254: v2(8.661,101.308) 12.205,101.308 v2(12.598,100.914)
NetC9_1: C9.1 D3.3 U1.6 | length 11.1
  Top Layer w0.254: v2(16.459,97.485) D3.3@17.719,97.485 ; U1.6@18.796,100.914 21.768,100.914 C9.1@21.819,100.965
  MidLayer2 w0.254: v2(16.459,97.485) 18.39,97.485 v2(21.844,100.94)
NetC12_1: C12.1 D5.1 Q1.3 U2.3 | length 7.2
  Top Layer w0.254: U2.3@38.698,115.82 38.855,115.976 D5.1@40.97,115.976 ; D5.1@41.107,116.114 Q1.3@43.561,116.114 43.561,117.983 C12.1@43.917,118.339
NetC14_1: C14.1 J1.10 R13.1 | length 17.9
  Top Layer w0.254: C14.1@8.222,18.826 R13.1@9.823,18.826 10.696,17.953 12.1,17.953 12.6,18.453 12.6,20.241 13.712,21.353 16.053,21.353 17.6,22.9 17.6,26.25 J1.10@16.38,27.47
NetC15_1: C15.1 J1.9 R14.1 | length 10.6
  Top Layer w0.254: C15.1@8.222,20.401 9.823,20.401 R14.1@9.848,20.426 9.848,21.448 10.5,22.1 13.55,22.1 J1.9@16.38,24.93
NetC28_1: C28.1 R19.2 S1.2 U3.10 | length 34.9
  Top Layer w0.254: S1.2@9.8,16.2 9.8,16.8 10.5,17.5 12.3,17.5 13.1,18.3 13.1,20.1 13.9,20.9 17.1,20.9 18.6,19.4 23.145,19.4 26.226,16.319 29.146,16.319 C28.1@29.947,17.12 ; R19.2@29.959,15.596 29.947,15.608 C28.1@29.947,17.12 ; U3.10@33.76,21.688 32.432,21.688 31.634,20.89 31.634,17.537 31.217,17.12 C28.1@29.947,17.12
NetC32_1: C32.1 R46.2 R49.2 U5.3 | length 11.8
  Top Layer w0.254: R49.2@148.3,16.75 v3(151.25,16.75) ; v4(155.7,17.8) 156.13,17.8 ; C32.1@156.135,16.815 C32.1@156.2,16.75 R46.2@156.2,15.25
  Top Layer w0.5: C32.1@156.135,16.815 U5.3@156.135,18.775
  Bottom Layer w0.254: v3(151.25,16.75) 154.65,16.75 v4(155.7,17.8)
NetC33_1: C33.1 C105.1 R115.1 R128.2 U12.2 | length 12.5
  Top Layer w0.254: R128.2@141.05,29.75 C105.1@142.8,28 142.8,26.127 142.25,25.577 142.25,25.385 142.058,25.385 ; U12.2@141.125,25.385 142.058,25.385 ; R115.1@144.45,21.25 C33.1@142.8,21.25 142.25,21.8 142.25,25.193 142.058,25.385
NetC34_1: C34.1 R65.2 R68.2 U7.3 | length 7.8
  Top Layer w0.254: R68.2@148,44.3 R65.2@148,46.4 149,47.4 150.175,47.4 151.05,46.525 150.865,46.34 U7.3@150.865,44.7
NetC35_1: C35.1 R84.2 R87.2 U9.3 | length 7.8
  Top Layer w0.254: R87.2@148,76.05 R84.2@148,78.15 149,79.15 150.175,79.15 151.05,78.275 150.865,78.09 U9.3@150.865,76.45
NetC36_1: C36.1 R103.2 R106.2 U11.3 | length 7.8
  Top Layer w0.254: R106.2@148,107.8 R103.2@148,109.9 149,110.9 150.175,110.9 151.05,110.025 150.865,109.84 U11.3@150.865,108.2
NetC37_2: C37.2 C49.1
NetC38_2: C38.2 C50.1
NetC39_2: C39.2@22.2,49.136 C45.1 | length 1.7
  Top Layer w0.508: C39.2@22.2,49.136 22.225,49.162 C45.1@22.225,50.787
NetC40_2: C40.2 C52.1
NetC41_2: C41.2 C53.1
NetC43_2: C43.2 C46.1 | length 1.9
  Top Layer w0.508: C46.1@175.92,66.573 C43.2@175.92,68.478
NetC51_2: C51.2 C57.1 | length 1.7
  Top Layer w0.508: C51.2@20.168,50.787 20.193,50.762 C57.1@20.193,49.136
NetC55_2: C55.2 C58.1 | length 1.9
  Top Layer w0.508: C58.1@175.895,58.522 C55.2@175.895,60.427
NetC60_1: C60.1 R20.1 | length 1.5
  Top Layer w0.5: R20.1@80,4.888 C60.1@80,6.412
NetC69_1: C69.1 R21.1 | length 1.5
  Top Layer w0.5: R21.1@80,36.538 C69.1@80,38.062
NetC78_1: C78.1 R22.1 | length 1.5
  Top Layer w0.5: R22.1@80,68.288 C78.1@80,69.812
NetC87_1: C87.1 R23.1 | length 1.5
  Top Layer w0.5: R23.1@80,100.038 C87.1@80,101.562
NetC99_1: C99.1 R109.2 R110.1 | length 4.6
  Top Layer w0.254: R109.2@136,26.05 136,27.266 C99.1@136.734,28 137.5,27.234 137.5,26.3 R110.1@137.75,26.05
NetC100_1: C100.1 R110.2 R111.1 | length 2.6
  Top Layer w0.254: 137.484,22.126 137.484,22.534 R111.1@137.95,23 137.75,23.2 R110.2@137.75,24.45
NetC101_1: C101.1 R113.2 R114.1 | length 4.2
  Top Layer w0.508: R114.1@151.5,26.55 151.5,27.984 C101.1@152.016,28.5 153.05,28.5 R113.2@153.75,29.2
NetC102_1: C102.1 R114.2 U12.6 | length 5.6
  Top Layer w0.2: U12.6@146.375,24.115 146.375,24.001 148.599,24.001 148.713,24.115 149.381,24.115 C102.1@149.75,24.484
  Top Layer w0.254: C102.1@149.75,24.484 150.216,24.95 R114.2@151.5,24.95
NetC104_1: C104.1 U5.5 | length 1.9
  Top Layer w0.254: U5.5@157.405,24.225 157.405,25.605 C104.1@157.75,25.95
NetC106_2: C106.2 R49.1 R51.2 TP20.1 U15.1 | length 7.9
  Top Layer w0.5: C106.2@145.05,20 145.25,19.8 145.25,18.25 R51.2@146.7,18.25 ; R49.1@146.7,16.75 R51.2@146.7,18.25 ; TP20.1@148.25,20.75 146.7,19.2 R51.2@146.7,18.25
NetC108_2: C108.2 R87.1 R89.2 TP46.1 U16.1 | length 22
  Top Layer w0.254: v3(149.75,74) 149.3,74.45 R87.1@148,74.45 148,73.4 147.701,73.101 147.701,72.453 147.685,72.437 147.685,71.815 148.25,71.25 148.25,69 149.75,67.5 150.55,67.5 R89.2@150.75,67.3 ; v4(153,74) 153.5,74 154,74.5 TP46.1@156,74.5 154.95,75.55 C108.2@154.95,76.75 154.55,77.15 U16.1@154.55,78.3
  MidLayer2 w0.254: v4@152.863,74 v4(153,74)
  Bottom Layer w0.254: v3(149.75,74) v4(153,74)
NetC109_2: C109.2 R68.1 R70.2 TP33.1 U17.1 | length 22
  Top Layer w0.254: v3(149.75,42.25) 149.3,42.7 R68.1@148,42.7 148,41.5 147.5,41 147.5,40.011 148.5,39.011 148.5,37 149.95,35.55 R70.2@150.75,35.55 ; v4(153,42.25) 153.5,42.75 TP33.1@156,42.75 154.95,43.8 C109.2@154.95,45 154.55,45.4 U17.1@154.55,46.55
  Bottom Layer w0.254: v3(149.75,42.25) v4(153,42.25)
NetC112_2: C112.2 R106.1 R108.2 TP57.1 U18.1 | length 21.9
  Top Layer w0.254: v3(149.75,105.75) 149.3,106.2 R106.1@148,106.2 148,105.2 147.4,104.6 147.4,103.661 148.594,102.467 148.594,100.728 150,99.322 150.478,99.322 R108.2@150.75,99.05 ; v8(152.75,105.75) 153.25,106.25 TP57.1@156,106.25 154.95,107.3 C112.2@154.95,108.5 154.55,108.9 U18.1@154.55,110.05
  Bottom Layer w0.254: v3(149.75,105.75) v8(152.75,105.75)
NetC114_2: C114.2 R122.2 | length 1.5
  Top Layer w0.5: R122.2@46.05,110.25 47.45,110.25 C114.2@47.5,110.3
NetD1_1: D1.1 R122.1 T1.4 | length 8.6
  Top Layer w0.508: T1.4@38.416,106.734 38.416,108.647 39.139,109.37 D1.1@41.57,109.37 43.57,109.37 R122.1@44.45,110.25
NetD2_1: D2.1 R1.1 | length 1.9
  Top Layer w0.3: R1.1@59.8,7.5 D2.1@61.7,7.5
NetD4_1: D4.1 R5.1 T1.2 T1.3 | length 6.7
  Top Layer w0.508: T1.3@38.416,104.734 T1.2@38.416,102.734 38.474,102.791 D4.1@41.544,102.791 41.529,102.806 R5.1@41.529,104.343
NetD6_1: D6.1 Q1.2 R8.2 | length 3.6
  Top Layer w0.254: R8.2@44.386,112.471 R8.2@44.437,112.522 ; Q1.2@44.511,114.214 44.511,112.596 R8.2@44.437,112.522 ; D6.1@46.279,112.522 R8.2@44.437,112.522
NetD7_1: D7.1 R9.1 | length 3.1
  Top Layer w0.254: D7.1@30.886,118.5 30.937,118.55 R9.1@30.937,119.977 ; D7.1@30.886,118.652 30.886,120.206 R9.1@30.937,120.256
NetD8_1: D8.1 Q4.4 Q8.4 Q12.3 R34.2 | length 18.6
  Top Layer w0.5: Q12.3@138.25,14.55 139.05,13.75 139.05,13.551 ; Q4.4@139.276,5.405 140.895,5.405 v10(140.9,5.4) ; Q8.4@139.276,11.405 139.05,11.631 R34.2@139.05,13 140,13 v10(140.25,12.75) 140.25,13.887 D8.1@141.75,15.388
  MidLayer2 w0.5: v10(140.25,12.75) 140.25,12 139,10.75 139,6 139.6,5.4 v10(140.9,5.4)
NetD8_2: D8.2 Q4.1 Q4.2 Q4.3 Q8.1 Q8.2 Q8.3 R27.1 R36.1 R46.1 | length 27.5
  Top Layer w0.2: 151.997,15.7 152.002,15.7 152.326,16.024 153.574,16.024 153.749,15.849 153.749,15.252 153.751,15.25 153.751,14.651 153.926,14.476 157.026,14.476 R46.1@157.8,15.25
  Top Layer w0.25: R36.1@142.55,9.5 142.55,8.45 143.5,7.5 146.5,7.5 146.75,7.75 146.75,15.35 147.1,15.7 151.997,15.7
  Top Layer w0.5: D8.2@141.75,12.113 142.55,11.312 142.55,11.276
  other v1: 140.5,2.25 140.5,3.5 143.75,5 143.75,6.25 140.62,8.108 143.75,9 140.62,9.608 143.75,10.5
NetD9_2: D9.2 Q15.1 R41.1 | length 9.4
  Top Layer w0.5: R41.1@134.25,23.2 134.25,20.687 D9.2@134.1,20.538 135.333,20.538 135.971,19.9 135.971,16.298 135.7,16.027 Q15.1@135.7,15.45
NetD10_1: D10.1 Q7.4 Q20.4 Q23.3 R56.2 | length 19.4
  Top Layer w0.254: R56.2@134,47.45 133.939,47.389 Q7.4@133.939,45.541 133.939,44.568 134.092,44.416 140,44.416 ; Q20.4@140.086,45.541 140,45.455 140,44.416 ; Q23.3@146.588,41.2 146.588,42.524 D10.1@146,43.112 146,44 145.584,44.416 140,44.416
NetD10_2: D10.2 Q7.1 Q7.2 Q7.3 Q20.1 Q20.2 Q20.3 R52.1 R57.1 R65.1 | length 17.1
  Top Layer w0.25: R57.1@142.75,57.95 142.75,56.25 146.75,56.25 147.07,55.93 147.07,55.638 147.074,55.634 147.074,49.366 147.07,49.362 147.07,48.23 147.3,48 R65.1@148,48 ; v1(143.922,46.702) 144.236,46.387 D10.2@146,46.387
  Top Layer w0.254: v1@135.209,47.591 v1@135.235,47.591
  other v1: 139,45.5 135.209,46.702 136.505,46.702 137.775,46.702 141.382,46.702 142.652,46.702 139,46.75 135.209,47.845 136.479,47.845 137.775,47.845 138.969,47.845 140.162,47.845 141.382,47.845 142.652,47.845 143.922,47.845 139,53 141.5,53 140.25,53.75 139,54.25 141.5,54.25 140.25,55 139,55.5 141.5,55.75 140.25,56.25 139,56.75 141.5,57 140.25,57.5 139,58 141.5,58.25 140.25,58.75 141.5,59.5
NetD11_2: D11.2 Q25.1 R63.1 | length 4.2
  Top Layer w0.254: Q25.1@135.95,60.45 135.95,60.812 D11.2@137.388,62.25 137.887,62.75 R63.1@138.95,62.75
NetD12_1: D12.1 Q26.4 Q30.4 Q34.3 R75.2 | length 19.4
  Top Layer w0.254: R75.2@134,79.2 134,77.352 Q26.4@133.939,77.291 133.939,76.318 134.092,76.166 140,76.166 ; Q30.4@140.086,77.291 140,77.205 140,76.166 ; Q34.3@146.588,72.95 146.588,74.274 D12.1@146,74.862 146,75.75 145.584,76.166 140,76.166
NetD12_2: D12.2 Q26.1 Q26.2 Q26.3 Q30.1 Q30.2 Q30.3 R71.1 R76.1 R84.1 | length 16.6
  Top Layer w0.25: R76.1@142.75,89.7 142.75,88 146.6,88 147.07,87.53 147.07,80.672 R84.1@147.992,79.75
  Top Layer w0.254: v1@135.209,79.341 v1@135.235,79.341
  Top Layer w0.508: v1(143.922,78.452) 144.236,78.137 D12.2@146,78.137
  other v1: 138.75,77.25 135.209,78.452 136.505,78.452 137.775,78.452 141.382,78.452 142.652,78.452 139,78.5 140,78.75 135.209,79.595 136.479,79.595 137.775,79.595 138.969,79.595 140.162,79.595 141.382,79.595 142.652,79.595 143.922,79.595 139,84.75 141.5,84.75 140.25,85.5 139,86 141.5,86 140.25,86.75 139,87.25 141.5,87.5 140.25,88 139,88.5 141.5,88.75 140.25,89.25 139,89.75 141.5,90 140.25,90.5 141.5,91.25
NetD13_1: D13.1 Q5.1 Q16.1 Q16.2 Q16.3 | length 0.9
  Top Layer w0.5: Q5.1@89.408,16.078 Q5.1@89.408,16.944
